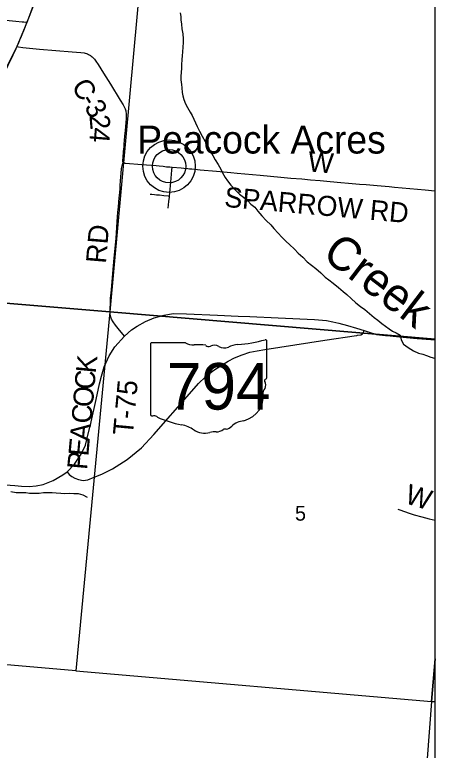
# Model space of a CAD drawing. Extents: x 0 to 1134, y 0 to 440.
# Drawn here: x 845.172 to 846.364, y 356.8 to 358.883 of the extents above; entities that cross this region are included whole.
import ezdxf

# ---------------------------------------------------------------- set-up
doc = ezdxf.new("R2010")
doc.units = 0
for name, color, linetype in [('Default', 7, 'Continuous'), ('GM_X_County_Road', 7, 'Continuous'), ('GM_X_County_Road_Text', 7, 'Continuous'), ('GM_X_Minor_River', 7, 'Continuous'), ('GM_X_Minor_River_Text', 7, 'Continuous'), ('GM_X_Rail_Line', 7, 'Continuous'), ('GM_X_Section', 7, 'Continuous'), ('GM_X_Section_Text', 7, 'Continuous'), ('GM_X_State_Location', 7, 'Continuous'), ('GM_X_State_Shield', 7, 'Continuous'), ('GM_X_Township_Road', 7, 'Continuous'), ('GM_X_Township_Road_Text', 7, 'Continuous'), ('GM_X_Unincorporated', 7, 'Continuous'), ('GM_X_Unincorporated_Location', 7, 'Continuous'), ('GM_X_Unincorporated_Text', 7, 'Continuous'), ('GM_X_US_Route', 7, 'Continuous'), ('SH_Cut_Line', 7, 'Continuous')]:
    doc.layers.add(name, color=color, linetype=linetype)

msp = doc.modelspace()

# ---------------------------------------------------------------- linework, layer by layer
at = {"layer": 'Default'}
for points in [[(846.3638, 357.9637), (846.3638, 358.929), (845.53, 359.0106), (845.441, 358.0413)], [(846.3638, 357.0584), (846.3638, 357.9637), (845.441, 358.0413), (845.3453, 357.0247), (846.3532, 356.9374)], [(846.3638, 356.9364), (846.3638, 357.0584), (846.3532, 356.9374)], [(846.3638, 355.8995), (846.3638, 356.9364), (846.3532, 356.9374), (846.2747, 355.9077)]]:
    msp.add_lwpolyline(points, close=True, dxfattribs=at)
at = {"layer": 'GM_X_County_Road'}
for points in [[(845.1783, 358.793), (845.1829, 358.7922), (845.1945, 358.7901), (845.2045, 358.789), (845.2416, 358.7858), (845.3346, 358.7782), (845.3594, 358.7761), (845.3687, 358.7747), (845.3718, 358.7741), (845.3748, 358.7732), (845.3778, 358.7721), (845.3807, 358.7707), (845.3861, 358.7675), (845.3887, 358.7657), (845.3912, 358.7637), (845.3935, 358.7615), (845.3977, 358.7569), (845.4016, 358.7519), (845.4087, 358.7417), (845.4235, 358.7179), (845.4428, 358.686), (845.471, 358.6413), (845.4791, 358.6276), (845.4819, 358.6224), (845.4844, 358.6166), (845.4864, 358.6106), (845.4871, 358.6075), (845.4875, 358.6044), (845.4878, 358.598), (845.4873, 358.5887), (845.4845, 358.5546), (845.4832, 358.5392), (845.482, 358.5269), (845.4813, 358.5177), (845.4806, 358.5084), (845.4793, 358.4958), (845.4777, 358.4774), (845.4771, 358.4713), (845.4771, 358.4698), (845.4773, 358.4683), (845.4776, 358.4672), (845.4783, 358.4659), (845.4794, 358.4647)], [(845.4794, 358.4647), (845.4804, 358.464), (845.4825, 358.4631), (845.484, 358.4628), (845.4855, 358.4626), (845.532, 358.4589), (845.5723, 358.4555), (845.5815, 358.4547), (845.5922, 358.4537), (845.6022, 358.4526), (845.6102, 358.4521), (845.6179, 358.4512)], [(845.6179, 358.4512), (845.6433, 358.4489), (845.6506, 358.4482), (845.6625, 358.4471), (845.6667, 358.4468), (845.6734, 358.4462), (845.6973, 358.444), (845.7437, 358.4398), (845.784, 358.436), (845.8025, 358.4343), (845.8675, 358.4284), (845.9263, 358.4229), (845.9541, 358.4205), (845.9851, 358.4178), (846.0098, 358.4157), (846.0377, 358.4133), (846.0655, 358.4109), (846.0965, 358.4082), (846.1182, 358.4062), (846.1491, 358.4034), (846.1677, 358.4019), (846.1986, 358.3993), (846.2327, 358.3963), (846.2482, 358.3949), (846.3132, 358.3891), (846.3348, 358.3872), (846.3627, 358.3846), (846.3638, 358.3845)], [(845.4825, 357.9727), (845.5032, 357.9904), (845.5191, 358.0009), (845.5422, 358.014), (845.5672, 358.0245), (845.5949, 358.0322), (845.6212, 358.0363), (845.6589, 358.0354), (845.7465, 358.0317), (845.805, 358.0295), (845.8386, 358.0281), (845.9185, 358.0249), (846.0211, 358.0199), (846.0552, 358.0172), (846.0733, 358.0136), (846.0906, 358.0095), (846.1146, 358.0027), (846.1405, 357.9954), (846.1626, 357.9882)], [(845.3202, 357.5887), (845.3411, 357.61), (845.3602, 357.6382), (845.372, 357.6636), (845.3788, 357.6917), (845.3865, 357.7213), (845.4029, 357.7934), (845.4124, 357.8379), (845.4178, 357.8597), (845.4256, 357.8856), (845.4392, 357.9164), (845.4551, 357.9419), (845.4825, 357.9727)], [(846.1626, 357.9882), (846.1764, 357.9836), (846.1972, 357.9777), (846.2225, 357.9743), (846.2358, 357.9732), (846.2627, 357.9709), (846.3122, 357.9663), (846.3638, 357.9619)], [(844.5843, 357.6033), (844.5908, 357.6022), (844.6028, 357.6), (844.6121, 357.5988), (844.643, 357.5958), (844.6833, 357.5922), (844.7204, 357.5888), (844.7667, 357.5846), (844.7915, 357.5826), (844.8348, 357.5788), (844.8905, 357.5736), (844.9401, 357.5692), (844.9741, 357.5664), (845.0267, 357.5618), (845.0608, 357.559), (845.1196, 357.5538), (845.1723, 357.5492), (845.1913, 357.5474), (845.2127, 357.5465), (845.2322, 357.5488), (845.2522, 357.5524), (845.2808, 357.5637), (845.308, 357.5796), (845.3202, 357.5887)]]:
    msp.add_lwpolyline(points, dxfattribs=at)
at = {"layer": 'GM_X_Minor_River'}
for points in [[(845.6405, 358.8882), (845.6423, 358.8783), (845.643, 358.8685), (845.6444, 358.8559), (845.6458, 358.843), (845.6483, 358.8293), (845.6489, 358.8145), (845.6492, 358.8043), (845.6487, 358.7914), (845.647, 358.7778), (845.6462, 358.7664), (845.6457, 358.7561), (845.6448, 358.7406), (845.6443, 358.7304), (845.6435, 358.7205), (845.6422, 358.7084), (845.6429, 358.6981), (845.6443, 358.6856), (845.6453, 358.6757), (845.6467, 358.6628), (845.6485, 358.6533), (845.651, 358.6426), (845.6562, 358.6308), (845.6614, 358.6205), (845.6693, 358.6068), (845.6745, 358.5973), (845.6793, 358.5873), (845.6845, 358.5771), (845.6889, 358.5668), (845.6956, 358.553), (845.7031, 358.5393), (845.7112, 358.5237), (845.7161, 358.5141), (845.722, 358.5046), (845.728, 358.4939), (845.7336, 358.4844), (845.7403, 358.4721), (845.7485, 358.4588), (845.7556, 358.4458), (845.7611, 358.4348), (845.7678, 358.4218), (845.7746, 358.4122), (845.7843, 358.4), (845.7959, 358.3881), (845.809, 358.3751), (845.8199, 358.3666), (845.832, 358.3563)], [(845.832, 358.3563), (845.8413, 358.3467), (845.8526, 358.3378), (845.8608, 358.3264), (845.8717, 358.313), (845.8844, 358.3), (845.8972, 358.2877), (845.9066, 358.2773), (845.9182, 358.2647), (845.9287, 358.2525), (845.941, 358.2402), (845.9508, 358.2321), (845.9643, 358.2191), (845.9756, 358.208), (845.9883, 358.1961), (846.0003, 358.1834), (846.0131, 358.1738), (846.0255, 358.1642), (846.039, 358.1515), (846.0514, 358.14), (846.062, 358.1323), (846.0744, 358.1227), (846.089, 358.1101), (846.1029, 358.0989), (846.1127, 358.0905), (846.1258, 358.0789), (846.1386, 358.0674), (846.1517, 358.0567), (846.1638, 358.0478), (846.1777, 358.0367), (846.1904, 358.0255), (846.2006, 358.0182), (846.2126, 358.0086), (846.2228, 358.0009), (846.2326, 357.9932), (846.2427, 357.9863), (846.2533, 357.9816), (846.2646, 357.9755), (846.2675, 357.9625), (846.2738, 357.9499), (846.2873, 357.9403), (846.3016, 357.9314), (846.316, 357.9245), (846.3284, 357.9213), (846.339, 357.9181), (846.3515, 357.9135), (846.3617, 357.9099), (846.3638, 357.9091)], [(845.1608, 357.5329), (845.1763, 357.5297), (845.2036, 357.5294), (845.2134, 357.5282), (845.227, 357.5281), (845.2407, 357.5283), (845.2536, 357.5293), (845.2657, 357.5296), (845.2774, 357.5294), (845.2892, 357.5289), (845.302, 357.5281), (845.3126, 357.5268), (845.327, 357.5274), (845.3391, 357.5273), (845.352, 357.5268), (845.3652, 357.5232), (845.3773, 357.517)]]:
    msp.add_lwpolyline(points, dxfattribs=at)
at = {"layer": 'GM_X_Rail_Line'}
msp.add_lwpolyline([(846.3458, 361.5102), (846.106, 361.002), (846.0456, 360.8726), (845.8559, 360.2141), (845.7851, 360.0449), (845.7229, 359.9444), (845.6533, 359.8622), (845.5758, 359.7804), (845.5564, 359.7595), (845.5217, 359.6718), (845.4977, 359.6064), (845.3993, 359.3625), (845.2065, 358.8608), (845.178, 358.7931), (844.9566, 358.3533), (844.582, 357.6032), (844.3357, 357.1113), (844.0901, 356.6196), (843.8375, 356.1142)], dxfattribs=at)
at = {"layer": 'GM_X_Section'}
for points in [[(844.5175, 359.0975), (845.4793, 359.0162), (845.53, 359.0106), (845.441, 358.0413), (844.4326, 358.1255)], [(844.4326, 358.1255), (845.441, 358.0413), (845.3453, 357.0247), (844.3449, 357.1111)]]:
    msp.add_lwpolyline(points, close=True, dxfattribs=at)
at = {"layer": 'GM_X_State_Shield'}
for p, q in [((845.5565, 357.9506), (845.5565, 357.7504)), ((845.6562, 357.954), (845.5597, 357.954)), ((845.8861, 357.8543), (845.8861, 357.959)), ((845.886, 357.8543), (845.8861, 357.8543))]:
    msp.add_line(p, q, dxfattribs=at)
for centre, major_axis, start_param, end_param in [((845.5602, 357.951), (0.00382, 0), 1.712693, 3.28349), ((845.6792, 357.9772), (0.037, 0), 4.042523, 4.731795), ((845.7686, 358.2268), (0.3495, 0), 4.814394, 5.042369), ((845.8824, 357.9594), (0.00367, 0), 6.141152, 7.989035), ((845.6915, 357.8417), (0.133, 0), 1.404758, 1.657858), ((845.7217, 357.952), (0.0107, 0), 3.836095, 5.185415), ((845.7374, 357.9289), (0.0222, 0), 0.950623, 2.079405), ((845.766, 357.9606), (0.0267, 0), 4.081561, 5.145723), ((845.8132, 357.8929), (0.0703, 0), 1.699011, 2.107814), ((845.8852, 357.8466), (0.00568, 0), 1.883978, 3.671073), ((845.8821, 357.8539), (0.00393, 0), 5.05454, 6.418171), ((845.8992, 357.8105), (0.0248, 0), 2.387724, 3.262537), ((845.8491, 357.8334), (0.0341, 0), 5.934695, 6.695948), ((845.7882, 357.7972), (0.0874, 0), 5.101752, 6.440018), ((845.5603, 357.75), (0.00385, 0), 3.00124, 4.508301), ((845.5609, 357.7705), (0.0294, 0), 4.665946, 4.897461), ((845.5669, 357.7389), (0.0106, 0), 0.519207, 1.627899), ((845.7007, 357.9187), (0.2524, 0), 4.195997, 4.488961), ((845.6255, 357.6605), (0.079, 0), 0.823519, 1.323587), ((845.8251, 357.6943), (0.0479, 0), 1.647645, 2.488434), ((845.7109, 357.7379), (0.0501, 0), 4.026481, 4.996735), ((845.7398, 357.6687), (0.0412, 0), 1.495662, 1.94098), ((845.7435, 357.7229), (0.0267, 0), 4.691044, 5.507374), ((845.7676, 357.7035), (0.00752, 0), 1.147584, 2.315152), ((845.7644, 357.7311), (0.0282, 0), 4.937069, 5.64225)]:
    msp.add_ellipse(centre, major_axis=major_axis, ratio=0.8, start_param=start_param, end_param=end_param, dxfattribs=at)
at = {"layer": 'GM_X_Township_Road'}
for points in [[(844.9632, 358.7842), (844.9688, 358.7998), (844.9706, 358.8057), (844.9717, 358.8105), (844.9727, 358.8164), (844.9738, 358.8241), (844.9753, 358.8395), (844.9777, 358.8673), (844.9784, 358.8733), (844.9791, 358.8762), (844.9801, 358.879), (844.9812, 358.8806), (844.9828, 358.8819), (844.9842, 358.8824), (844.9866, 358.8826), (844.9932, 358.8822), (845.0054, 358.881), (845.0208, 358.8795), (845.0424, 358.8775), (845.1748, 358.8651), (845.1932, 358.8633), (845.1975, 358.8628), (845.2033, 358.8617), (845.2063, 358.8611)], [(845.4825, 357.9727), (845.4646, 357.9943), (845.4571, 358.0034), (845.451, 358.0127), (845.446, 358.0211), (845.4435, 358.029), (845.4424, 358.0372), (845.4436, 358.079), (845.4458, 358.1038), (845.4501, 358.1501), (845.4539, 358.1934), (845.4588, 358.249), (845.4612, 358.28), (845.4623, 358.297), (845.4633, 358.3107), (845.4644, 358.3233), (845.4658, 358.3384), (845.4679, 358.364), (845.4692, 358.3782), (845.4703, 358.3912), (845.471, 358.4001), (845.4719, 358.4117), (845.4748, 358.4468), (845.4753, 358.4511), (845.4759, 358.4546), (845.4772, 358.4591), (845.4794, 358.4647)], [(845.6104, 358.3693), (845.6112, 358.3781), (845.6138, 358.4087), (845.617, 358.4423), (845.6179, 358.4512)], [(845.5553, 358.3752), (845.5602, 358.3749), (845.5681, 358.374), (845.5736, 358.3733), (845.5825, 358.3725), (845.5946, 358.3711), (845.6064, 358.3698), (845.6104, 358.3693)], [(845.6065, 358.3354), (845.6088, 358.3537), (845.6101, 358.3659), (845.6104, 358.3693)], [(845.3202, 357.5887), (845.3259, 357.5808), (845.3335, 357.5747), (845.3422, 357.5702), (845.3524, 357.5664), (845.3656, 357.5641), (845.3785, 357.566), (845.3971, 357.5736), (845.4187, 357.5816), (845.4493, 357.5971), (845.4906, 357.6228), (845.5312, 357.6566), (845.566, 357.6937), (845.6675, 357.8096), (845.6925, 357.8383), (845.7126, 357.8577), (845.7334, 357.8739), (845.7565, 357.8899), (845.7766, 357.902), (845.7951, 357.9114), (845.8167, 357.9198), (845.8383, 357.927), (845.8591, 357.9311), (845.8807, 357.9349), (846.0504, 357.9611), (846.1405, 357.9746), (846.1413, 357.9747), (846.1433, 357.975), (846.1523, 357.9766), (846.1576, 357.9792), (846.1595, 357.9815), (846.1626, 357.9882)], [(846.2575, 357.4828), (846.2635, 357.481), (846.2896, 357.471), (846.3043, 357.4662), (846.3252, 357.4604), (846.3463, 357.4553), (846.3638, 357.4517)]]:
    msp.add_lwpolyline(points, dxfattribs=at)
at = {"layer": 'GM_X_Unincorporated'}
msp.add_lwpolyline([(846.3638, 355.7181), (846.3638, 358.9291)], dxfattribs=at)
for radius in [0.0744, 0.0472]:
    msp.add_circle((845.6092, 358.4539), radius, dxfattribs=at)
at = {"layer": 'GM_X_Unincorporated_Location'}
msp.add_line((845.6092, 358.4539), (845.6092, 358.4539), dxfattribs=at)
at = {"layer": 'GM_X_US_Route'}
for points in [[(845.2063, 358.8611), (845.2096, 358.8696), (845.218, 358.8922), (845.2325, 358.9314), (845.2404, 358.9531), (845.2489, 358.9762), (845.2649, 359.02), (845.2686, 359.0298), (845.2757, 359.0491), (845.2946, 359.0985), (845.3049, 359.1245), (845.3143, 359.1484), (845.3207, 359.1648), (845.345, 359.2256), (845.3785, 359.31)], [(845.0622, 358.5581), (845.0681, 358.5698), (845.0766, 358.5871), (845.0955, 358.6248), (845.1148, 358.6631), (845.128, 358.6901), (845.1528, 358.7403), (845.165, 358.7649), (845.167, 358.769), (845.1758, 358.7874), (845.1783, 358.793), (845.1789, 358.7942), (845.1823, 358.8017), (845.1864, 358.8118), (845.1908, 358.8221), (845.2013, 358.848), (845.2063, 358.8611)]]:
    msp.add_lwpolyline(points, dxfattribs=at)
at = {"layer": 'SH_Cut_Line'}
msp.add_lwpolyline([(846.3638, 355.7181), (846.3638, 369.3181)], dxfattribs=at)

# ---------------------------------------------------------------- texts
at = {"layer": 'GM_X_County_Road_Text'}
for s, height, rotation, p in [('C', 0.0568, 301.5755, (845.3308, 358.6806)), ('-', 0.0568, 301.5073, (845.3552, 358.6409)), ('3', 0.0568, 301.1838, (845.3673, 358.621)), ('2', 0.0568, 275.0074, (845.3833, 358.5976)), ('4', 0.0568, 265.3373, (845.3864, 358.5652)), ('W', 0.0568, 354.9366, (846.001, 358.4396)), ('SPARROW RD', 0.05682, 354.9297, (845.7643, 358.339))]:
    msp.add_text(s, height=height, rotation=rotation, dxfattribs=at).set_placement(p)
at = {"layer": 'GM_X_Minor_River_Text'}
msp.add_text('Creek', height=0.09469, rotation=322.6025, dxfattribs=at).set_placement((846.0393, 358.1966))
at = {"layer": 'GM_X_Section_Text'}
msp.add_text('5', height=0.0419, rotation=0, dxfattribs=at).set_placement((845.9661, 357.45))
at = {"layer": 'GM_X_State_Location'}
for s, p in [('s', (845.7176, 357.8372)), ('r', (845.7175, 357.8372))]:
    msp.add_text(s, height=0.000189, dxfattribs=at).set_placement(p)
msp.add_text('794', height=0.000189, rotation=0, dxfattribs=at).set_placement((845.6507, 357.8234))
at = {"layer": 'GM_X_State_Shield'}
msp.add_text('794', height=0.13184, dxfattribs=at).set_placement((845.603, 357.7646))
at = {"layer": 'GM_X_Township_Road_Text'}
for s, height, rotation, p in [('RD', 0.05682, 85.1579, (845.4301, 358.1769)), ('K', 0.0568, 84.3006, (845.4013, 357.8657)), ('C', 0.0568, 84.845, (845.3971, 357.8194)), ('T-75', 0.05682, 84.6682, (845.5064, 357.69)), ('O', 0.0568, 84.8641, (845.3927, 357.7696)), ('C', 0.0568, 84.8646, (845.3885, 357.7231)), ('A', 0.0568, 84.8643, (845.384, 357.6733)), ('E', 0.0568, 84.8632, (845.3802, 357.631)), ('P', 0.0568, 84.8662, (845.3768, 357.5928)), ('W', 0.0568, 342.4898, (846.2744, 357.5007))]:
    msp.add_text(s, height=height, rotation=rotation, dxfattribs=at).set_placement(p)
at = {"layer": 'GM_X_Unincorporated_Text'}
msp.add_text('Peacock Acres', height=0.078977, rotation=0, dxfattribs=at).set_placement((845.519, 358.4898))

doc.saveas('drawing.dxf')
